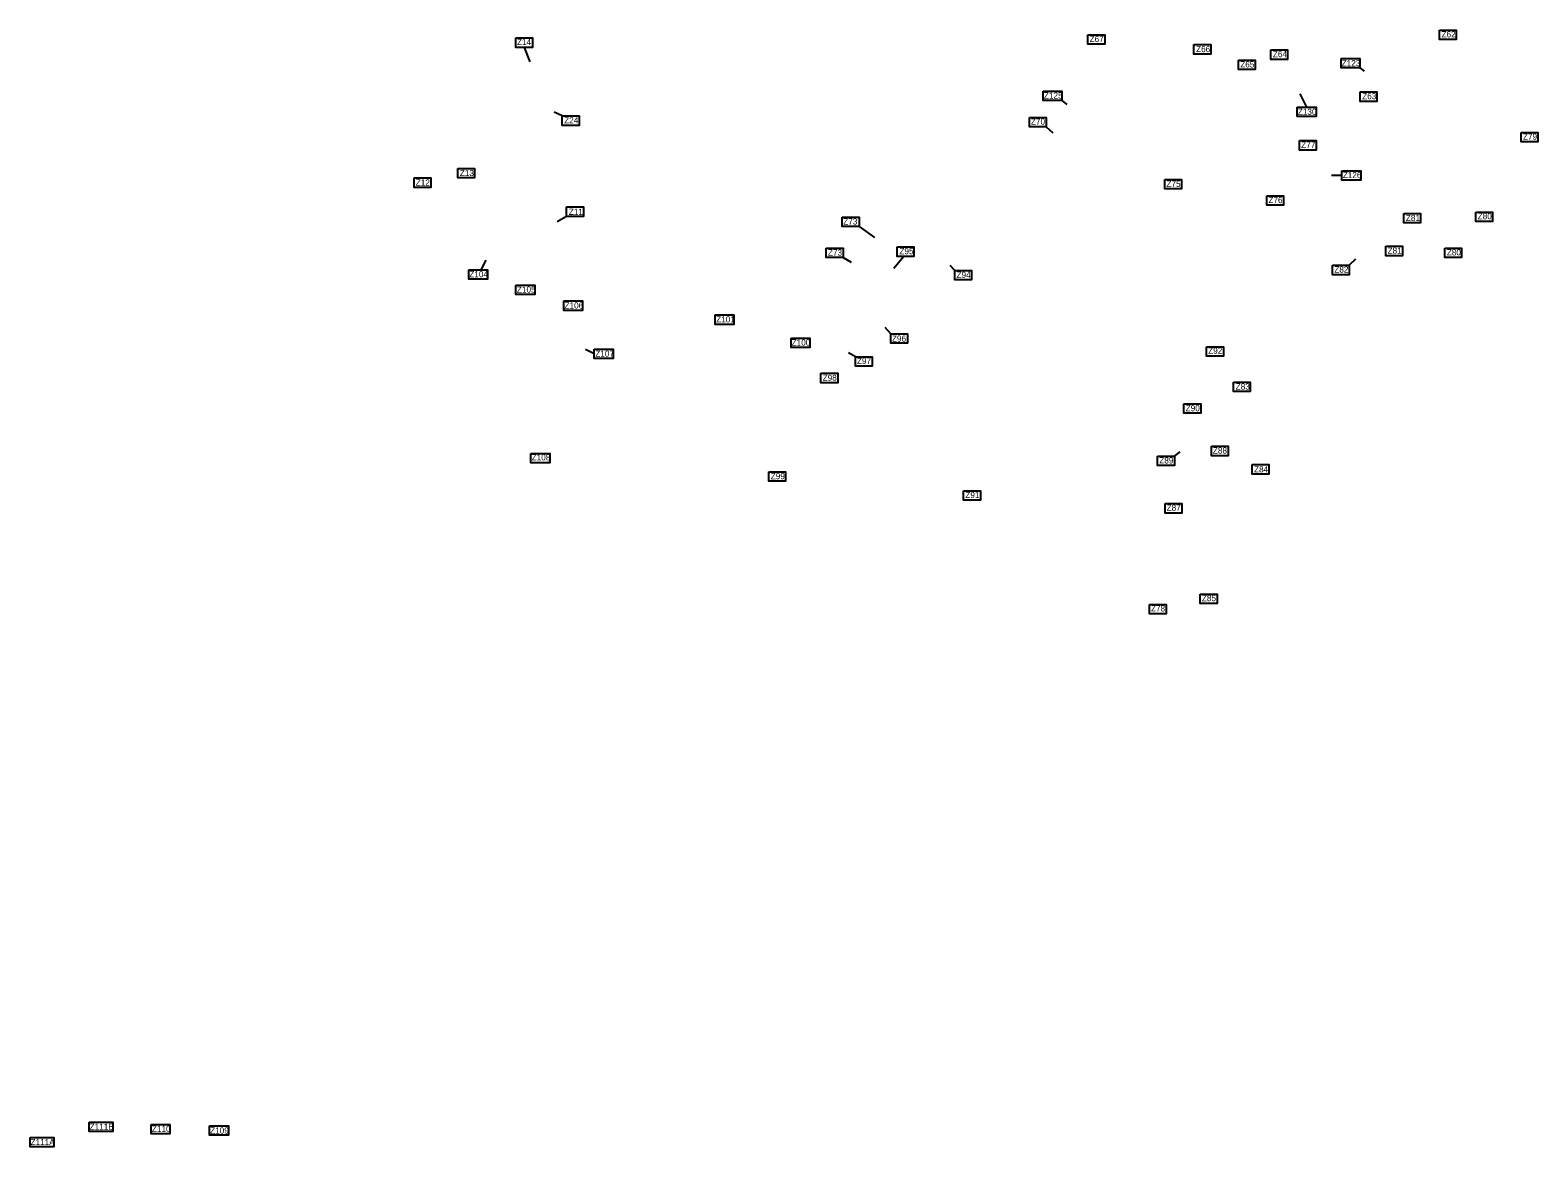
# Model space of a CAD drawing. Extents: x -443483 to -430840, y -1135277 to -1129797.
# Drawn here: x -443483 to -441026, y -1133472 to -1131650 of the extents above; entities that cross this region are included whole.
import ezdxf

# ---------------------------------------------------------------- set-up
doc = ezdxf.new("R2010")
doc.units = 0
doc.layers.add('Vrstva 3', color=7, linetype='Continuous')
doc.layers.add('Vrstva 8', color=7, linetype='Continuous')

msp = doc.modelspace()

# ---------------------------------------------------------------- linework, layer by layer
at = {"layer": 'Vrstva 3'}
for p, q in [((-442678, -1131678.5), (-442668.8, -1131701.8)), ((-442615.8, -1131790.2), (-442629.3, -1131783.8)), ((-441826.8, -1131808), (-441816.1, -1131818)), ((-442608.7, -1131954), (-442624.4, -1131962.9)), ((-442132.1, -1131970.6), (-442106.7, -1131988.4)), ((-442748.1, -1132041), (-442739.9, -1132025.7)), ((-442158.1, -1132021.3), (-442145, -1132028.8)), ((-442059.1, -1132019.3), (-442075.2, -1132039)), ((-441976.2, -1132042.2), (-441983.4, -1132034.2)), ((-441332.9, -1132033.8), (-441322.2, -1132023.2)), ((-442080.4, -1132145.5), (-442089.6, -1132135.5)), ((-442563.8, -1132178.3), (-442578.2, -1132171.1)), ((-442137.9, -1132182.9), (-442149.2, -1132176.8)), ((-441618.1, -1132344.9), (-441608.8, -1132338.2))]:
    msp.add_line(p, q, dxfattribs=at)
for points in [[(-442691.7, -1131663.1), (-442664.4, -1131663.1), (-442664.4, -1131678.5), (-442691.7, -1131678.5)], [(-441758.9, -1131657.7), (-441731.5, -1131657.7), (-441731.5, -1131673.1), (-441758.9, -1131673.1)], [(-441186, -1131650.3), (-441158.6, -1131650.3), (-441158.6, -1131665.7), (-441186, -1131665.7)], [(-441586.1, -1131673.9), (-441558.7, -1131673.9), (-441558.7, -1131689.3), (-441586.1, -1131689.3)], [(-441460.9, -1131682.5), (-441433.5, -1131682.5), (-441433.5, -1131697.9), (-441460.9, -1131697.9)], [(-441513.5, -1131699.1), (-441486.1, -1131699.1), (-441486.1, -1131714.5), (-441513.5, -1131714.5)], [(-441315.3, -1131751.1), (-441287.9, -1131751.1), (-441287.9, -1131766.5), (-441315.3, -1131766.5)], [(-442615.8, -1131790.2), (-442588.4, -1131790.2), (-442588.4, -1131805.6), (-442615.8, -1131805.6)], [(-441854.2, -1131792.6), (-441826.8, -1131792.6), (-441826.8, -1131808), (-441854.2, -1131808)], [(-441414.1, -1131830.4), (-441386.7, -1131830.4), (-441386.7, -1131845.8), (-441414.1, -1131845.8)], [(-441053, -1131817.2), (-441025.6, -1131817.2), (-441025.6, -1131832.6), (-441053, -1131832.6)], [(-442786.3, -1131876), (-442759, -1131876), (-442759, -1131891.4), (-442786.3, -1131891.4)], [(-442857.4, -1131891.3), (-442830, -1131891.3), (-442830, -1131906.7), (-442857.4, -1131906.7)], [(-441633.7, -1131893.9), (-441606.4, -1131893.9), (-441606.4, -1131909.3), (-441633.7, -1131909.3)], [(-442608.7, -1131938.6), (-442581.4, -1131938.6), (-442581.4, -1131954), (-442608.7, -1131954)], [(-441467.5, -1131920.6), (-441440.1, -1131920.6), (-441440.1, -1131936), (-441467.5, -1131936)], [(-442159.4, -1131955.2), (-442132.1, -1131955.2), (-442132.1, -1131970.6), (-442159.4, -1131970.6)], [(-441244, -1131949.4), (-441216.7, -1131949.4), (-441216.7, -1131964.8), (-441244, -1131964.8)], [(-441126.7, -1131946.9), (-441099.4, -1131946.9), (-441099.4, -1131962.3), (-441126.7, -1131962.3)], [(-442185.4, -1132005.9), (-442158.1, -1132005.9), (-442158.1, -1132021.3), (-442185.4, -1132021.3)], [(-442069.9, -1132003.9), (-442042.5, -1132003.9), (-442042.5, -1132019.3), (-442069.9, -1132019.3)], [(-441273.5, -1132002.7), (-441246.1, -1132002.7), (-441246.1, -1132018.1), (-441273.5, -1132018.1)], [(-441177.4, -1132005.6), (-441150, -1132005.6), (-441150, -1132021), (-441177.4, -1132021)], [(-441360.2, -1132033.8), (-441332.9, -1132033.8), (-441332.9, -1132049.2), (-441360.2, -1132049.2)], [(-442768.4, -1132041), (-442737.7, -1132041), (-442737.7, -1132056.4), (-442768.4, -1132056.4)], [(-441976.2, -1132042.2), (-441948.8, -1132042.2), (-441948.8, -1132057.6), (-441976.2, -1132057.6)], [(-442691.5, -1132066.2), (-442660.7, -1132066.2), (-442660.7, -1132081.6), (-442691.5, -1132081.6)], [(-442613.5, -1132092), (-442582.8, -1132092), (-442582.8, -1132107.4), (-442613.5, -1132107.4)], [(-442366.7, -1132114.8), (-442336, -1132114.8), (-442336, -1132130.2), (-442366.7, -1132130.2)], [(-442242.9, -1132152.5), (-442212.2, -1132152.5), (-442212.2, -1132167.9), (-442242.9, -1132167.9)], [(-442080.4, -1132145.5), (-442053.1, -1132145.5), (-442053.1, -1132160.9), (-442080.4, -1132160.9)], [(-442563.8, -1132170.6), (-442533.1, -1132170.6), (-442533.1, -1132186), (-442563.8, -1132186)], [(-442137.9, -1132182.9), (-442110.5, -1132182.9), (-442110.5, -1132198.2), (-442137.9, -1132198.2)], [(-441565.6, -1132166.6), (-441538.2, -1132166.6), (-441538.2, -1132181.9), (-441565.6, -1132181.9)], [(-442194.3, -1132209.9), (-442166.9, -1132209.9), (-442166.9, -1132225.3), (-442194.3, -1132225.3)], [(-441521.7, -1132224.2), (-441494.3, -1132224.2), (-441494.3, -1132239.6), (-441521.7, -1132239.6)], [(-441602.6, -1132259.7), (-441575.2, -1132259.7), (-441575.2, -1132275.1), (-441602.6, -1132275.1)], [(-441557.5, -1132329), (-441530.2, -1132329), (-441530.2, -1132344.4), (-441557.5, -1132344.4)], [(-442667.1, -1132340.5), (-442636.3, -1132340.5), (-442636.3, -1132355.9), (-442667.1, -1132355.9)], [(-441645.5, -1132344.9), (-441618.1, -1132344.9), (-441618.1, -1132360.3), (-441645.5, -1132360.3)], [(-442279.2, -1132370.4), (-442251.8, -1132370.4), (-442251.8, -1132385.8), (-442279.2, -1132385.8)], [(-441491.3, -1132358.9), (-441463.9, -1132358.9), (-441463.9, -1132374.3), (-441491.3, -1132374.3)], [(-441961.6, -1132401.7), (-441934.2, -1132401.7), (-441934.2, -1132417.1), (-441961.6, -1132417.1)], [(-441633.3, -1132422.4), (-441605.9, -1132422.4), (-441605.9, -1132437.8), (-441633.3, -1132437.8)], [(-441575.8, -1132570.2), (-441548.5, -1132570.2), (-441548.5, -1132585.5), (-441575.8, -1132585.5)], [(-441658.8, -1132586.9), (-441631.4, -1132586.9), (-441631.4, -1132602.3), (-441658.8, -1132602.3)], [(-443387, -1133431.3), (-443348.5, -1133431.3), (-443348.5, -1133446.7), (-443387, -1133446.7)], [(-443286.1, -1133434.8), (-443255.3, -1133434.8), (-443255.3, -1133450.2), (-443286.1, -1133450.2)], [(-443190.7, -1133437.1), (-443160, -1133437.1), (-443160, -1133452.5), (-443190.7, -1133452.5)], [(-443483.2, -1133456.1), (-443444.8, -1133456.1), (-443444.8, -1133471.5), (-443483.2, -1133471.5)], [(-443483.2, -1133456.1), (-443444.8, -1133456.1), (-443444.8, -1133471.5), (-443483.2, -1133471.5)]]:
    msp.add_lwpolyline(points, close=True, dxfattribs=at)
at = {"layer": 'Vrstva 8'}
for p, q in [((-441315.6, -1131712), (-441308.9, -1131717.3)), ((-441801.4, -1131765.3), (-441793.1, -1131771.6)), ((-441402.4, -1131775.9), (-441412.9, -1131754.3)), ((-441345, -1131887.4), (-441361.9, -1131887.4))]:
    msp.add_line(p, q, dxfattribs=at)
for points in [[(-441346.4, -1131696.6), (-441315.6, -1131696.6), (-441315.6, -1131712), (-441346.4, -1131712)], [(-441832.2, -1131749.9), (-441801.4, -1131749.9), (-441801.4, -1131765.3), (-441832.2, -1131765.3)], [(-441417.8, -1131775.9), (-441387.1, -1131775.9), (-441387.1, -1131791.3), (-441417.8, -1131791.3)], [(-441345, -1131879.7), (-441314.2, -1131879.7), (-441314.2, -1131895.1), (-441345, -1131895.1)]]:
    msp.add_lwpolyline(points, close=True, dxfattribs=at)

# ---------------------------------------------------------------- texts
at = {"layer": 'Vrstva 3'}
for s, p in [('Z14', (-442689.6, -1131674.5)), ('Z67', (-441756.2, -1131669.8)), ('Z62', (-441182.6, -1131662.1)), ('Z66', (-441582.7, -1131686.2)), ('Z64', (-441457.5, -1131694.4)), ('Z65', (-441510.7, -1131711.2)), ('Z63', (-441311.9, -1131762.9)), ('Z24', (-442612.7, -1131802.4)), ('Z70', (-441851.9, -1131804.4)), ('Z77', (-441411.3, -1131842.4)), ('Z79', (-441049.9, -1131829)), ('Z13', (-442782.8, -1131888.3)), ('Z12', (-442854.7, -1131903.8)), ('Z75', (-441631, -1131906)), ('Z76', (-441464.8, -1131932.4)), ('Z11', (-442605.2, -1131951.5)), ('Z73', (-442157.8, -1131967.3)), ('Z81', (-441240.7, -1131961.6)), ('Z80', (-441123.6, -1131958.7)), ('Z73', (-442182.8, -1132018)), ('Z95', (-442066.3, -1132015.8)), ('Z81', (-441270.5, -1132014.9)), ('Z80', (-441174, -1132017.7)), ('Z82', (-441357.4, -1132045.6)), ('Z104', (-442767.4, -1132053.3)), ('Z94', (-441973.2, -1132054.4)), ('Z105', (-442689.8, -1132078.4)), ('Z106', (-442612.2, -1132104.3)), ('Z101', (-442365, -1132127)), ('Z100', (-442242, -1132164.7)), ('Z96', (-442078.4, -1132158.3)), ('Z107', (-442562, -1132182.9)), ('Z92', (-441563, -1132178)), ('Z97', (-442135.5, -1132194.7)), ('Z98', (-442191.4, -1132222.2)), ('Z83', (-441518.1, -1132236.4)), ('Z90', (-441599.6, -1132271.8)), ('Z88', (-441555.3, -1132340.8)), ('Z108', (-442665.7, -1132352)), ('Z89', (-441642.7, -1132357)), ('Z99', (-442276, -1132382.7)), ('Z84', (-441488.2, -1132371.5)), ('Z91', (-441958.8, -1132413.4)), ('Z87', (-441630.7, -1132434.2)), ('Z85', (-441573.2, -1132581.6)), ('Z78', (-441656.2, -1132598.4)), ('Z111B', (-443386.3, -1133443.6)), ('Z110', (-443284.8, -1133447.1)), ('Z111A', (-443482.6, -1133468.7)), ('Z109', (-443189.9, -1133449.9))]:
    msp.add_text(s, height=10, dxfattribs=at).set_placement(p)
at = {"layer": 'Vrstva 8'}
for s, p in [('Z123', (-441345.4, -1131709.1)), ('Z125', (-441830.8, -1131761.9)), ('Z130', (-441416.9, -1131788.4)), ('Z126', (-441343.6, -1131891.7))]:
    msp.add_text(s, height=10, dxfattribs=at).set_placement(p)

doc.saveas('drawing.dxf')
